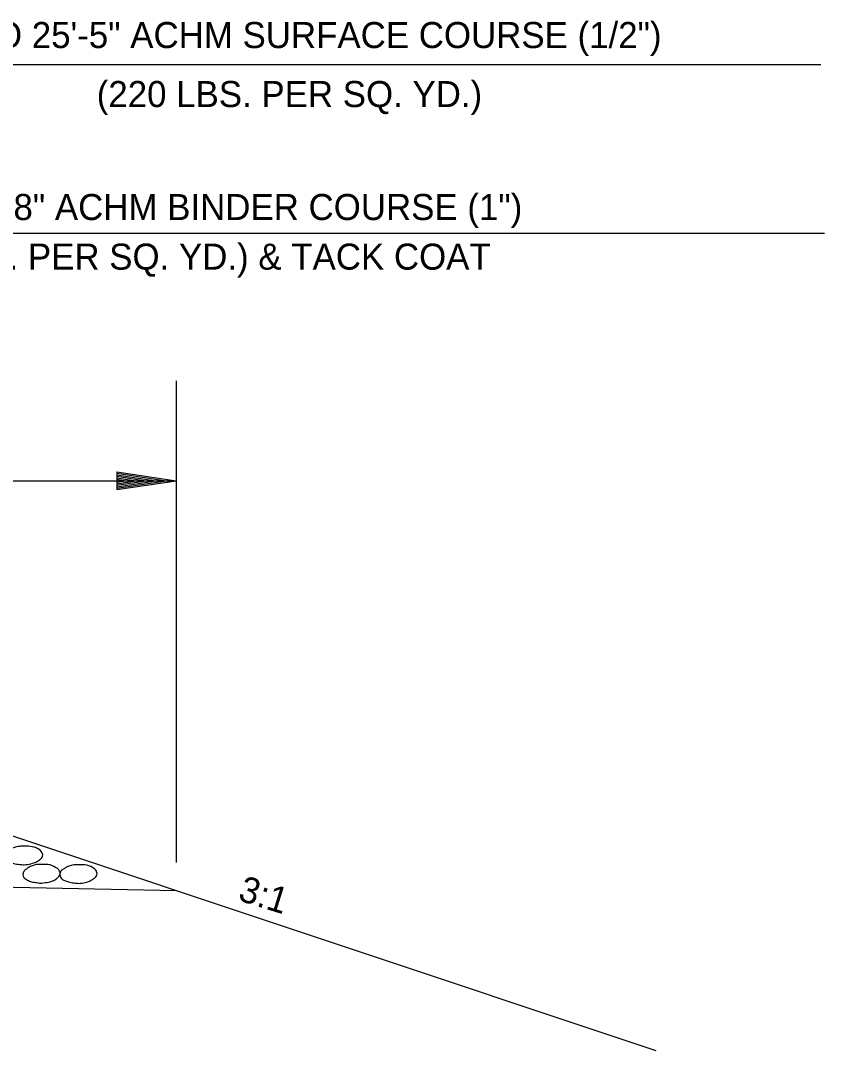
# Model space of a CAD drawing. Extents: x 836 to 5683, y -463 to 1545.
# Drawn here: x 4769.7 to 4954.8, y -344 to -107 of the extents above; entities that cross this region are included whole.
import ezdxf

# ---------------------------------------------------------------- set-up
doc = ezdxf.new("R2010")
doc.units = 0
doc.layers.add('Default', color=7, linetype='Continuous')

msp = doc.modelspace()

# ---------------------------------------------------------------- linework, layer by layer
at = {"layer": 'Default'}
for p, q in [((4953.92, -117.19), (4718.46, -117.19)), ((4954.76, -155.99), (4633.46, -155.99)), ((4805.51, -189.97), (4805.51, -300.81)), ((4791.83, -210.88), (4805.51, -212.92)), ((4791.83, -210.88), (4791.83, -214.98)), ((4718.46, -212.92), (4805.51, -212.92)), ((4791.83, -211.21), (4803.22, -212.92)), ((4791.83, -211.57), (4800.85, -212.92)), ((4791.83, -211.9), (4798.56, -212.92)), ((4791.83, -212.27), (4796.25, -212.92)), ((4791.83, -212.6), (4793.96, -212.92)), ((4791.83, -214.98), (4805.51, -212.92)), ((4791.83, -213.61), (4796.25, -212.92)), ((4791.83, -214.3), (4800.85, -212.92)), ((4791.83, -214.64), (4803.22, -212.92)), ((4791.83, -213.94), (4798.56, -212.92)), ((4791.83, -213.25), (4793.96, -212.92)), ((4718.46, -278.19), (4915.99, -344.03)), ((4471.56, -300.53), (4805.51, -307.21))]:
    msp.add_line(p, q, dxfattribs=at)
for points in [[(4770.41, -297.06), (4771.92, -297.07), (4773.76, -297.68), (4774.65, -298.55), (4774.79, -299.04), (4774.3, -300), (4773.77, -300.41), (4772.78, -300.86), (4771.3, -301.23), (4770.56, -301.3), (4769.43, -301.22), (4768.19, -301.01), (4767.26, -300.63), (4766.34, -299.91), (4766.23, -299.33), (4766.5, -298.52), (4767.17, -297.96), (4767.82, -297.52), (4768.82, -297.2), (4769.46, -297.07), (4770.41, -297.06)], [(4774.46, -301.26), (4775.96, -301.27), (4777.78, -301.91), (4778.7, -302.75), (4778.83, -303.28), (4778.34, -304.2), (4777.8, -304.62), (4776.85, -305.12), (4775.33, -305.43), (4774.6, -305.54), (4773.46, -305.42), (4772.25, -305.22), (4771.31, -304.83), (4770.41, -304.14), (4770.25, -303.53), (4770.54, -302.72), (4771.22, -302.16), (4771.88, -301.74), (4772.86, -301.43), (4773.48, -301.27), (4774.46, -301.26)], [(4782.94, -301.32), (4784.47, -301.33), (4786.29, -301.97), (4787.18, -302.8), (4787.3, -303.34), (4786.84, -304.26), (4786.32, -304.65), (4785.32, -305.17), (4783.86, -305.51), (4783.1, -305.59), (4781.99, -305.48), (4780.73, -305.27), (4779.78, -304.9), (4778.9, -304.17), (4778.75, -303.59), (4779.01, -302.77), (4779.71, -302.24), (4780.35, -301.82), (4781.37, -301.47), (4782, -301.33), (4782.94, -301.32)]]:
    msp.add_spline(points, degree=3, dxfattribs=at)

# ---------------------------------------------------------------- texts
for s, p in [('0\'-0" TO 25\'-5" ACHM SURFACE COURSE (1/2")', (4740.71, -113.35)), ('(220 LBS. PER SQ. YD.)', (4787.24, -126.93)), ('0\'-0" TO 21\'-8" ACHM BINDER COURSE (1")', (4723.36, -152.93)), ('(330 LBS. PER SQ. YD.) & TACK COAT', (4733.48, -164.35))]:
    msp.add_text(s, height=6, dxfattribs=at).set_placement(p)
msp.add_text('3:1', height=6, rotation=342.7185, dxfattribs=at).set_placement((4819.52, -309.42))

doc.saveas('drawing.dxf')
